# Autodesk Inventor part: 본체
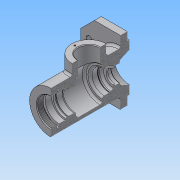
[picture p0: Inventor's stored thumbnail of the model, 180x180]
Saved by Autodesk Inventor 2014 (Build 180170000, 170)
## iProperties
Created: 2017-10
Part Number: 본체
Material: 일반
Document SubType Name: Modeling
Designer: NET
Density: 1 g/cm^3
Appearance: 기본값
Author: NET
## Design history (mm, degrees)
sketch "스케치1"
  geometry: L1 (-51, 0)-(51, 0); L2 (51, 0)-(51, 31); L3 (51, 31)-(-51, 31); L4 (-51, 31)-(-51, 0); 2 further points
  constraints: 8 end point, 3 perpendicular, 1 coincident, 1 horizontal, 1 midpoint
  dimensions: "d0" = 102 distance of L1.start L1.end; "d1" = 62 diameter of L3 L1
revolve "회전1" sketch "스케치1" stored, may be unused: angle "d2" = 90 deg
node "작업 평면1"
sketch "스케치2"
  geometry: L1 (31, -51)-(-31, -51) reference; L2 (31, 51)-(-31, 51) reference; C1 r 25 at (0, 5); 1 further point
  constraints: 1 centre point, 1 vertical alignment
  dimensions: "d4" = 50 diameter of C1; "d5" = 56 distance from line of L1 C1.centre
extrude "돌출1" join sketch "스케치2" stored distance "d6" = 10; taper "d7" = 0 deg
sketch "스케치3"
  geometry: L1 (-58, 47)-(58, 47); L2 (58, 47)-(58, -47); L3 (58, -47)-(-58, -47); L4 (-58, -47)-(-58, 47); C1 r 31 at (0, 0) reference; C2 r 35 at (0, 0); 2 further points
  constraints: 8 end point, 2 midpoint, 2 parallel, 1 centre point, 1 coincident, 1 horizontal, 1 horizontal alignment, 1 perpendicular, 1 vertical alignment
  dimensions: "d8" = 116 distance of L1.start L1.end; "d9" = 94 distance of L1.end L2.end; "d10" = 70 diameter of C2
extrude "돌출2" join sketch "스케치3" distance "d11" = 13; taper "d12" = 0 deg
extrude "돌출3" join sketch "스케치3" distance "d13" = 10; taper "d14" = 0 deg
sketch "스케치4"
  geometry: L1 (58, -47)-(58, 47) reference; L2 (46, -20)-(46, 20); L3 (50, -20)-(50, 20); L4 (42, 20)-(42, -20); L5 (-46, 20)-(-46, -20); L6 (-50, 20)-(-50, -20); L7 (-42, -20)-(-42, 20); C1 r 31 at (0, 0) reference; C2 r 31 at (0, 0) reference; A1 r 4 centre (46, -20) between (42, -20) and (50, -20); A2 r 4 centre (46, 20) between (50, 20) and (42, 20); A3 r 4 centre (-46, 20) between (-42, 20) and (-50, 20); A4 r 4 centre (-46, -20) between (-50, -20) and (-42, -20); 2 further points
  constraints: 16 end point, 8 point on circle, 8 tangent, 5 parallel, 4 centre point, 2 horizontal alignment, 2 midpoint
  dimensions: "d15" = 8 diameter of A2; "d16" = 8 diameter of A4; "d17" = 40 distance of L3.start L3.end; "d18" = 92 distance between parallel lines of L2 L5; "d19" = 46 distance of point (-46, 0) C1.centre
extrude "돌출4" cut sketch "스케치4" stored distance "d20" = 10; taper "d21" = 0 deg
sketch "스케치5"
  geometry: L1 (-51, -31)-(-51, 31) reference; L2 (64, -35)-(64, 35) reference; L3 (-51, 0)-(64, 0); L4 (-42, 0)-(-42, 24); L5 (-42, 24)-(-39, 24); L6 (-39, 24)-(-39, 20); L7 (-39, 20)-(-30, 20); L8 (-30, 20)-(-30, 17.5); L9 (-30, 17.5)-(-26.75, 17.5); L10 (-26.75, 17.5)-(-26.75, 18.5); L11 (-26.75, 18.5)-(-25, 18.5); L12 (-25, 18.5)-(-25, 17.5); L13 (-25, 17.5)-(-14, 17.5); L14 (-14, 17.5)-(-14, 26); L15 (-14, 26)-(24, 26); L16 (24, 26)-(24, 17.5); L17 (24, 17.5)-(35, 17.5); L18 (35, 17.5)-(35, 16.5); L19 (35, 16.5)-(40, 16.5); L20 (40, 16.5)-(40, 10); L21 (40, 10)-(42.7, 10); L22 (42.7, 10)-(42.7, 12.5); L23 (42.7, 12.5)-(49.3, 12.5); L24 (64, 0)-(64, 22); L25 (50, 12.904)-(50, 16); L26 (50, 16)-(64, 22); L27 (49.3, 12.5)-(50, 12.904); 2 further points
  constraints: 50 end point, 16 parallel, 3 perpendicular, 3 point on line, 2 collinear, 2 midpoint, 1 horizontal
  dimensions: "d27" = 38 distance of L14.end L15.end; "d28" = 60 distance between parallel lines of L18 L12; "d29" = 5 distance between parallel lines of L20 L18; "d30" = 2.7 distance between parallel lines of L22 L20; "d32" = 35 diameter of L13 L3; "d33" = 52 diameter of L15 L3; "d34" = 40 diameter of L7 L3; "d35" = 35 diameter of L9 L3; "d36" = 37 diameter of L11 L3; "d37" = 48 diameter of L5 L3; "d38" = 11 distance of L12.end L13.end; "d39" = 20 diameter of L21 L3; "d41" = 33 diameter of L19 L3; "d42" = 1.75 distance of L10.end L11.end; "d43" = 21 distance between parallel lines of L8 L1; "d44" = 9 distance between parallel lines of L4 L1; "d45" = 12 distance between parallel lines of L6 L1; "d46" = 26 distance between parallel lines of L12 L1; "d62" = 25 diameter of L23 L3; "d63" = 44 diameter of L24.end L3; "d64" = 32 diameter of L25.end L3; "d65" = 14 distance between parallel lines of L2 L25; "d75" = 30 deg angle of L27 L23; "d76" = 0.7 horizontal distance of L25.start L23.end
revolve "회전2" sketch "스케치5" stored, may be unused: angle "d47" = 90 deg
hole "구멍1" diameter "d50" = 32; stored, may be unused: countersink angle "d54" = 90 deg, drill point angle "d56" = 118 deg; dims "d51" = 6, "d52" = 4, "d53" = 2, "d55" = 8, "d57" = 10, "d58" = 10
sketch "스케치6"
  geometry: C1 r 16 at (0, 0) reference; 3 further points
  constraints: 2 horizontal alignment
  dimensions: "d59" = 41 distance of point (20.5, 0) point (-20.5, 0); "d60" = 20.5 distance of point (-20.5, 0) C1.centre
node "작업 평면2"
sketch "스케치8"
  geometry: L1 (-25, 0)-(25, 0) reference; L2 (-56, -78)-(-56, -16) reference; 2 further points
  constraints: 1 other
  dimensions: "d66" = 10 distance from line of point (0, -10) L1; "d67" = 56 distance from line of point (0, -10) L2
feature "엠보싱1" sketch "스케치8" dims "d0" = 102, "d1" = 62, "d8" = 116, "d9" = 94, "d68" = 0.5, "d69" = 0
chamfer "모따기1" distance "d70" = 20; stored, may be unused: second distance "d71" = 2, angle "d72" = 45 deg
hole "구멍2" sketch "스케치6" diameter "d77" = 2.459; stored, may be unused: countersink angle "d81" = 90 deg, drill point angle "d83" = 118 deg; dims "d78" = 6, "d79" = 4, "d80" = 2, "d82" = 8
hole "구멍3" diameter "d86" = 40.376; stored, may be unused: countersink angle "d90" = 90 deg, drill point angle "d92" = 0 deg; dims "d84" = 10, "d85" = 10, "d87" = 9, "d88" = 4, "d89" = 2, "d91" = 9
fillet "모깎기1" dims "d93" = 0.3
fillet "모깎기3" dims "d95" = 3
fillet "모깎기4" dims "d96" = 3
chamfer "모따기2" distance "d97" = 1; stored, may be unused: second distance "d98" = 2, angle "d99" = 45 deg
chamfer "모따기3" distance "d100" = 1; stored, may be unused: second distance "d101" = 2, angle "d102" = 45 deg
fillet "모깎기5" dims "d103" = 3
fillet "모깎기6" dims "d104" = 3
fillet "모깎기7" dims "d105" = 0.3
sketch "스케치7"
  geometry: C1 r 12.5 at (0, 0) reference; C2 r 35 at (0, 0) reference
node "솔리드1"
node "투영된 루프1"
node "투영된 루프2"
other parameters: "d3" = 47
